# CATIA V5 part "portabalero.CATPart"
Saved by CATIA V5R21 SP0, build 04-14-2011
Part number: portabalero
Bounding box of the stored display mesh (mm): x -35.75 to 35.75, y -35.554 to 35.554, z 0 to 12
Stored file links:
  C:\Users\A01166499\Desktop\Flippers\portabalero.CATPart
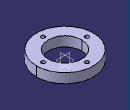
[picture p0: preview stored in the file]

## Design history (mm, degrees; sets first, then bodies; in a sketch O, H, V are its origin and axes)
Body1 (main body)
  Sketch1 on xy-plane, origin (0, 0, 0), H (1, 0, 0), V (0, 1, 0)
    circle A1 centre (0, 0) radius 35.75
    point P1 (0, 35.75)
    circle A2 centre (0, 0) radius 21
    radius A1 = 35.75
    radius A2 = 21
    coincidence: A1 P1, P1 V
  Pad1: profile Sketch1, direction (0, 0, 1), length 12
  Sketch2 on end face of Pad1, origin (0, 0, 12), H (1, 0, 0), V (0, 1, 0)
    circle A1 centre (0, 27.5) radius 2.5
    point P1 (0, 27.5)
    radius A1 = 2.5
    distance P1 H = 27.5
  Pocket1: profile Sketch2, direction (0, 0, -1), length 12
  CircPattern1: of Pocket1, instances 4, angular step 90, axis from Z axis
